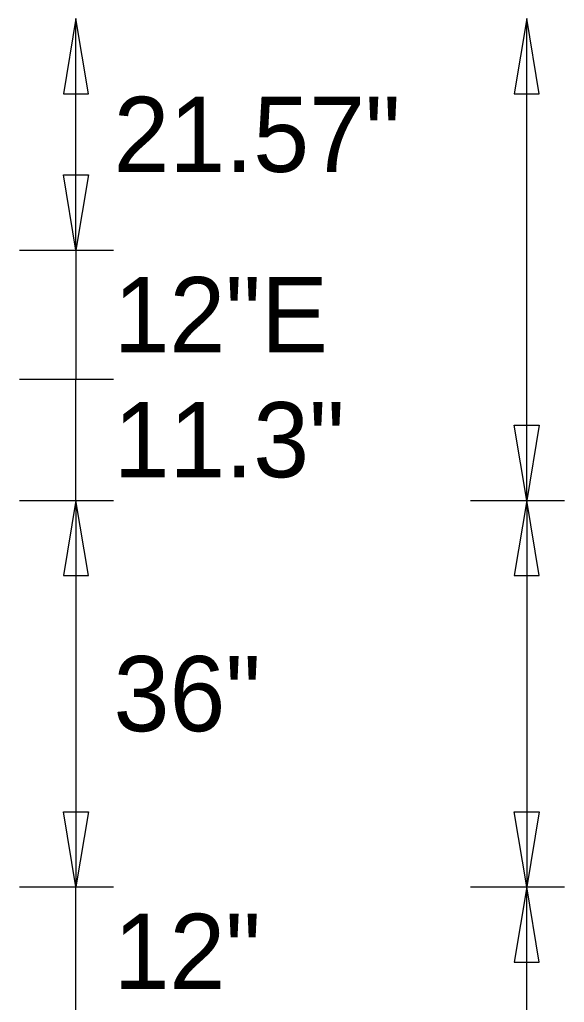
# Model space of a CAD drawing. Extents: x 2149934 to 2150188, y 145113 to 145238.
# Drawn here: x 2150047.75 to 2150051.98, y 145149.75 to 145157.37 of the extents above; entities that cross this region are included whole.
import ezdxf

# ---------------------------------------------------------------- set-up
doc = ezdxf.new("R2010")
doc.units = 0
doc.layers.add('GSDIMS', color=7, linetype='Continuous')

msp = doc.modelspace()

# ---------------------------------------------------------------- linework, layer by layer
at = {"layer": 'GSDIMS'}
for p, q in [((2150048.1866, 145155.5852), (2150048.1866, 145157.3827)), ((2150051.6866, 145153.6436), (2150051.6866, 145157.3827)), ((2150047.7491, 145155.5852), (2150048.4782, 145155.5852)), ((2150047.7491, 145155.5852), (2150048.4782, 145155.5852)), ((2150048.1866, 145155.5852), (2150048.1866, 145154.5852)), ((2150047.7491, 145154.5852), (2150048.4782, 145154.5852)), ((2150047.7491, 145154.5852), (2150048.4782, 145154.5852)), ((2150048.1866, 145153.6436), (2150048.1866, 145154.5852)), ((2150047.7491, 145153.6436), (2150048.4782, 145153.6436)), ((2150047.7491, 145153.6436), (2150048.4782, 145153.6436)), ((2150048.1866, 145153.6436), (2150048.1866, 145150.6435)), ((2150051.2491, 145153.6436), (2150051.9782, 145153.6436)), ((2150051.2491, 145153.6436), (2150051.9782, 145153.6436)), ((2150051.6866, 145153.6436), (2150051.6866, 145150.6435)), ((2150047.7491, 145150.6435), (2150048.4782, 145150.6435)), ((2150047.7491, 145150.6435), (2150048.4782, 145150.6435)), ((2150048.1866, 145149.6435), (2150048.1866, 145150.6435)), ((2150051.2491, 145150.6435), (2150051.9782, 145150.6435)), ((2150051.2491, 145150.6435), (2150051.9782, 145150.6435)), ((2150051.6866, 145144.3826), (2150051.6866, 145150.6435))]:
    msp.add_line(p, q, dxfattribs=at)
for points in [[(2150048.1866, 145157.3827), (2150048.0893, 145156.7994), (2150048.2838, 145156.7994)], [(2150051.6866, 145157.3827), (2150051.5893, 145156.7994), (2150051.7838, 145156.7994)], [(2150048.1866, 145155.5852), (2150048.0893, 145156.1686), (2150048.2838, 145156.1686)], [(2150051.6866, 145153.6436), (2150051.5893, 145154.2269), (2150051.7838, 145154.2269)], [(2150048.1866, 145153.6436), (2150048.0893, 145153.0603), (2150048.2838, 145153.0603)], [(2150051.6866, 145153.6436), (2150051.5893, 145153.0603), (2150051.7838, 145153.0603)], [(2150048.1866, 145150.6435), (2150048.0893, 145151.2268), (2150048.2838, 145151.2268)], [(2150051.6866, 145150.6435), (2150051.5893, 145151.2268), (2150051.7838, 145151.2268)], [(2150051.6866, 145150.6435), (2150051.5893, 145150.0602), (2150051.7838, 145150.0602)]]:
    msp.add_lwpolyline(points, close=True, dxfattribs=at)

# ---------------------------------------------------------------- texts
for s, p in [('21.57"', (2150048.4783, 145156.1923)), ('12"E', (2150048.4783, 145154.7935)), ('11.3"', (2150048.4783, 145153.8228)), ('36"', (2150048.4783, 145151.8519)), ('12"', (2150048.4783, 145149.8518))]:
    msp.add_text(s, height=0.58333, dxfattribs=at).set_placement(p)

doc.saveas('drawing.dxf')
